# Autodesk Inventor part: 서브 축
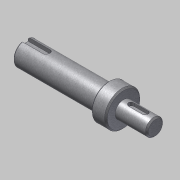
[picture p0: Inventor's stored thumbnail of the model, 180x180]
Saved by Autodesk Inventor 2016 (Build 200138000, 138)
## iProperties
Created: 2016-04
Part Number: 서브 축
Document SubType Name: Modeling
Designer: mdu
Density: 1 g/cm^3
Mass: 19.9624 g
Surface Area: 57.7178 cm^2
Volume: 19.9624 cm^3
Material: 강철, 연강
Appearance: 금속-강(스테인리스, 브러시됨)
Author: mdu
Revision Number: 1
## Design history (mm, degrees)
sketch "스케치1"
  geometry: L1 (-16.331, 0)-(-108.831, 0); L2 (-16.331, 0)-(-16.331, -6); L3 (-16.331, -6)-(-38.831, -6); L4 (-38.831, -12.5)-(-46.5, -12.5); L5 (-46.5, -8.5)-(-108.831, -8.5); L6 (-108.831, -8.5)-(-108.831, 0); L7 (-46.5, -8.5)-(-46.5, -12.5); L8 (-38.831, -6)-(-38.831, -12.5); L9 (-46.5, 12.249)-(-46.5, -12.249) reference; L10 (-38.831, -17)-(-38.831, 17) reference; 2 further points
  constraints: 17 end point, 4 perpendicular, 2 collinear, 2 parallel, 1 horizontal, 1 midpoint, 1 point on line
  dimensions: "d1" = 12 diameter of L3 L1; "d2" = 25 diameter of L4 L1; "d3" = 17 diameter of L5 L1; "d18" = 22.5 distance of L2.end L3.end; "d20" = 70 distance between parallel lines of L6 L8; "d21" = 7.66872 distance of L4.start L4.end (derived)
revolve "회전1" sketch "스케치1" stored, may be unused: angle "d5" = 90 deg
chamfer "모따기1" distance "d6" = 1; stored, may be unused: second distance "d7" = 2, angle "d8" = 45 deg
node "작업 평면1"
sketch "스케치2"
  geometry: L1 (11.25, 5)-(11.25, -5) reference; L2 (-5.75, -2)-(4.25, -2); L3 (4.25, 2)-(-5.75, 2); A1 r 2 centre (4.25, 0) between (4.25, -2) and (4.25, 2); A2 r 2 centre (-5.75, 0) between (-5.75, 2) and (-5.75, -2); 2 further points
  constraints: 4 end point, 4 point on circle, 4 tangent, 2 centre point, 1 horizontal alignment, 1 midpoint, 1 parallel, 1 perpendicular
  dimensions: "d9" = 4 distance between parallel lines of L2 L3; "d10" = 14 dimension on A1 A2; "d11" = 5 distance edge to line of A1 L1
extrude "돌출1" cut sketch "스케치2" distance "d12" = 2.5; taper "d13" = 0 deg
node "작업 평면2"
sketch "스케치3"
  geometry: L1 (-31.166, -7.5)-(-31.166, 7.5) reference; L2 (-31.166, 2.5)-(-15.666, 2.5); L3 (-15.666, -2.5)-(-31.166, -2.5); A1 r 2.5 centre (-15.666, 0) between (-15.666, -2.5) and (-15.666, 2.5); 2 further points
  constraints: 4 end point, 2 perpendicular, 2 point on circle, 2 point on line, 2 tangent, 1 centre point, 1 horizontal alignment, 1 midpoint
  dimensions: "d14" = 5 distance between parallel lines of L3 L2; "d15" = 18 dimension on A1 L1
extrude "돌출2" cut sketch "스케치3" distance "d16" = 3; taper "d17" = 0 deg
sketch "스케치4"
  geometry: C1 r 12.5 at (0, 0) reference; 1 further point
extrude "돌출3" join sketch "스케치4" distance "d22" = 3; taper "d23" = 0 deg
chamfer "모따기2" distance "d24" = 1; stored, may be unused: second distance "d25" = 2, angle "d26" = 45 deg
node "솔리드1"
node "참조4"
node "참조5"
